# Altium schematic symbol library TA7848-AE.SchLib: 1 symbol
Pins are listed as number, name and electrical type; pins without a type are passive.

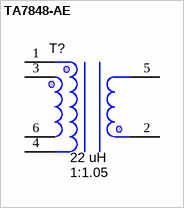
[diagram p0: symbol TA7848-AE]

## TA7848-AE
designator T?  value 22 uH  Turns Ratio: 1:1.05  (hidden comment: TA7848-AE)
Coupled Inductor, 22uH, 1.35A Irms, 2A Isat, 1:1.05 turns ratio, LPH8045 Hexagonal Package; Manufacturer: Coilcraft
footprint LPH8045-223 (SMD, 6-Leads, Body 8.76x8.05mm)
pins: 1, 2, 3, 4, 5, 6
